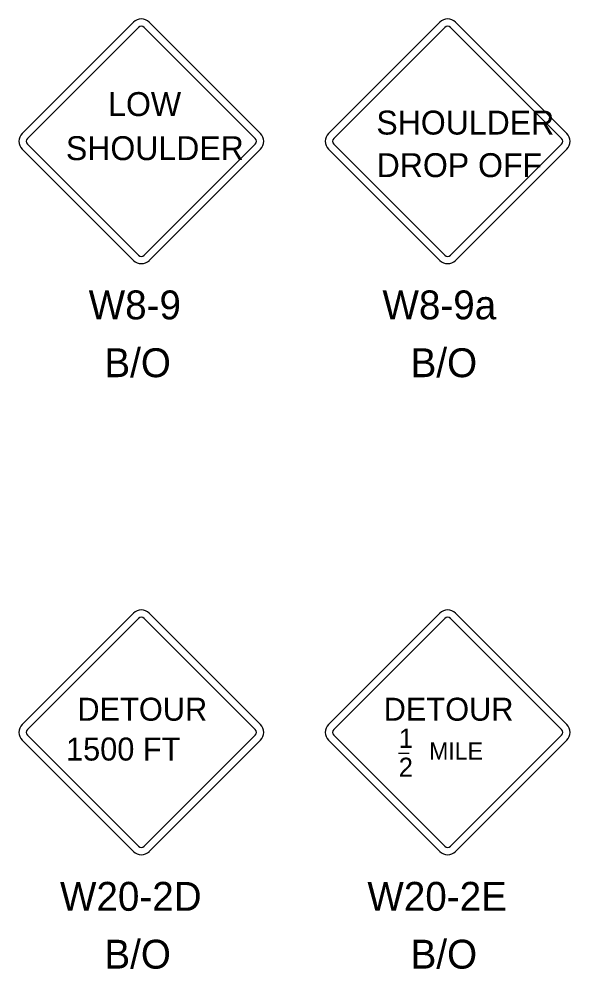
# Model space of a CAD drawing. Extents: x 10034 to 10794, y 10044 to 10499.
# Drawn here: x 10727.1 to 10793.8, y 10279.5 to 10394.6 of the extents above; entities that cross this region are included whole.
import ezdxf

# ---------------------------------------------------------------- set-up
doc = ezdxf.new("R2010")
doc.units = 0
for name, color, linetype in [('DSIndex', 7, 'Continuous'), ('DSText', 7, 'Continuous'), ('DSTitle', 7, 'Continuous'), ('PlotBorder_dp', 7, 'Continuous')]:
    doc.layers.add(name, color=color, linetype=linetype)

msp = doc.modelspace()

# ---------------------------------------------------------------- linework, layer by layer
at = {"layer": 'DSIndex'}
for p, q in [((10764.58, 10380.78), (10778.05, 10394.25)), ((10779.97, 10394.25), (10793.44, 10380.78)), ((10765.2, 10380.17), (10778.66, 10393.62)), ((10779.36, 10393.62), (10792.82, 10380.17)), ((10778.05, 10365.39), (10764.58, 10378.86)), ((10778.66, 10366.01), (10765.2, 10379.47)), ((10792.82, 10379.47), (10779.36, 10366.01)), ((10793.44, 10378.86), (10779.97, 10365.39)), ((10764.58, 10309.13), (10778.05, 10322.61)), ((10779.97, 10322.61), (10793.44, 10309.13)), ((10765.2, 10308.52), (10778.66, 10321.98)), ((10779.36, 10321.98), (10792.82, 10308.52)), ((10778.66, 10294.37), (10765.2, 10307.83)), ((10792.82, 10307.83), (10779.36, 10294.37)), ((10778.05, 10293.74), (10764.58, 10307.22)), ((10793.44, 10307.22), (10779.97, 10293.75)), ((10773.04, 10305.67), (10774.35, 10305.67))]:
    msp.add_line(p, q, dxfattribs=at)
for centre, radius, start, end in [((10779.01, 10393.29), 1.36, 45, 135), ((10779.01, 10393.28), 0.49, 45, 135), ((10765.54, 10379.82), 1.36, 135, 225), ((10765.55, 10379.82), 0.49, 135, 225), ((10792.47, 10379.82), 0.49, 315, 45), ((10792.48, 10379.82), 1.36, 315, 45), ((10779.01, 10366.35), 1.36, 225, 315), ((10779.01, 10366.36), 0.49, 225, 315), ((10779.01, 10321.65), 1.36, 45, 135), ((10779.01, 10321.64), 0.49, 45, 135), ((10765.54, 10308.18), 1.36, 135, 225), ((10765.55, 10308.18), 0.49, 135, 225), ((10792.47, 10308.18), 0.49, 315, 45), ((10792.48, 10308.18), 1.36, 315, 45), ((10779.01, 10294.7), 1.36, 225, 315), ((10779.01, 10294.72), 0.49, 225, 315)]:
    msp.add_arc(centre, radius, start, end, dxfattribs=at)
at = {"layer": 'DSText'}
for p, q in [((10727.46, 10380.77), (10740.94, 10394.25)), ((10742.85, 10394.25), (10756.33, 10380.77)), ((10740.94, 10365.39), (10727.46, 10378.86)), ((10756.33, 10378.86), (10742.85, 10365.39)), ((10727.46, 10309.13), (10740.94, 10322.61)), ((10742.85, 10322.61), (10756.32, 10309.13)), ((10740.94, 10293.74), (10727.46, 10307.22)), ((10756.32, 10307.22), (10742.85, 10293.74))]:
    msp.add_line(p, q, dxfattribs=at)
for centre, start, end in [((10741.89, 10393.29), 45, 135), ((10728.42, 10379.82), 135, 225), ((10755.36, 10379.82), 315, 45), ((10741.9, 10366.35), 225, 315), ((10741.89, 10321.65), 45, 135), ((10728.42, 10308.18), 135, 225), ((10755.36, 10308.18), 315, 45), ((10741.9, 10294.7), 225, 315)]:
    msp.add_arc(centre, 1.36, start, end, dxfattribs=at)
at = {"layer": 'DSTitle'}
for p, q in [((10728.09, 10380.17), (10741.55, 10393.62)), ((10742.24, 10393.62), (10755.7, 10380.17)), ((10741.55, 10366.01), (10728.09, 10379.47)), ((10755.7, 10379.47), (10742.24, 10366.01)), ((10728.09, 10308.52), (10741.54, 10321.98)), ((10742.24, 10321.98), (10755.7, 10308.52)), ((10741.54, 10294.37), (10728.09, 10307.83)), ((10755.7, 10307.83), (10742.24, 10294.37))]:
    msp.add_line(p, q, dxfattribs=at)
for centre, start, end in [((10741.89, 10393.28), 45, 135), ((10728.43, 10379.82), 135, 225), ((10755.35, 10379.82), 315, 45), ((10741.89, 10366.36), 225, 315), ((10741.89, 10321.64), 45, 135), ((10728.43, 10308.18), 135, 225), ((10755.35, 10308.18), 315, 45), ((10741.89, 10294.72), 225, 315)]:
    msp.add_arc(centre, 0.49, start, end, dxfattribs=at)

# ---------------------------------------------------------------- texts
at = {"layer": 'DSIndex'}
for s, height, p in [('SHOULDER', 2.901, (10770.37, 10380.64)), ('DROP OFF', 2.901, (10770.41, 10375.48)), ('W8-9a', 3.5, (10771.11, 10358.24)), ('B/O', 3.5, (10774.52, 10351.23)), ('DETOUR', 2.786, (10771.26, 10309.59)), ('1', 2.32, (10773.09, 10306.3)), ('MILE', 2.089, (10776.77, 10304.86)), ('2', 2.32, (10773.08, 10302.79)), ('W20-2E', 3.5, (10769.28, 10286.55)), ('B/O', 3.5, (10774.52, 10279.54))]:
    msp.add_text(s, height=height, dxfattribs=at).set_placement(p)
at = {"layer": 'PlotBorder_dp'}
for s, height, p in [('LOW', 2.902, (10737.87, 10382.88)), ('SHOULDER', 2.901, (10732.75, 10377.54)), ('W8-9', 3.5, (10735.51, 10358.24)), ('B/O', 3.5, (10737.41, 10351.23)), ('DETOUR', 2.786, (10734.14, 10309.59)), ('1500 FT', 2.786, (10732.76, 10304.76)), ('W20-2D', 3.5, (10732.03, 10286.55)), ('B/O', 3.5, (10737.41, 10279.54))]:
    msp.add_text(s, height=height, dxfattribs=at).set_placement(p)

doc.saveas('drawing.dxf')
